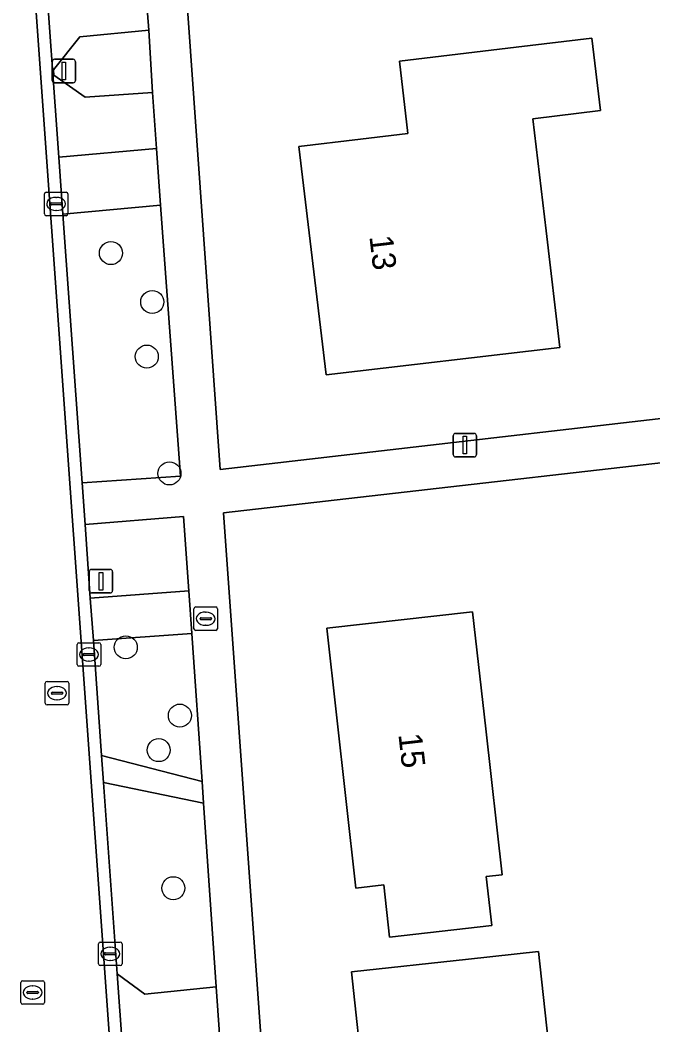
# Model space of a CAD drawing. Extents: x 162661 to 163484, y 380247 to 381230.
# Drawn here: x 163028.8 to 163055.7, y 380630.33 to 380673.06 of the extents above; entities that cross this region are included whole.
import ezdxf

# ---------------------------------------------------------------- set-up
doc = ezdxf.new("R2010")
doc.units = 0
for name, color, linetype in [('IMGEO_Boom', 7, 'Continuous'), ('IMGEO_Brandkraan', 7, 'Continuous'), ('IMGEO_Erf', 7, 'Continuous'), ('IMGEO_Groenvoorziening', 7, 'Continuous'), ('IMGEO_Kolk', 7, 'Continuous'), ('IMGEO_Lichtmast', 7, 'Continuous'), ('IMGEO_Pand', 7, 'Continuous'), ('IMGEO_Pand_nummerreeks', 7, 'Continuous'), ('IMGEO_Rijbaan_lokaal_gesloten', 7, 'Continuous'), ('IMGEO_Rijbaan_lokaal_open', 7, 'Continuous'), ('IMGEO_Rioolput', 7, 'Continuous'), ('IMGEO_Voetpad_halfverhard', 7, 'Continuous'), ('IMGEO_Voetpad_open', 7, 'Continuous')]:
    doc.layers.add(name, color=color, linetype=linetype)

msp = doc.modelspace()

# ---------------------------------------------------------------- linework, layer by layer
at = {"layer": 'IMGEO_Boom'}
for centre in [(163032.664, 380663.15), (163034.421, 380661.073), (163034.19, 380658.75), (163035.153, 380653.782), (163033.297, 380646.386), (163035.594, 380643.483), (163034.695, 380642.014), (163035.315, 380636.144)]:
    msp.add_circle(centre, 0.489, dxfattribs=at)
at = {"layer": 'IMGEO_Brandkraan'}
for p, q in [((163036.194, 380647.178), (163036.194, 380648.03)), ((163036.269, 380648.104), (163037.121, 380648.104)), ((163037.195, 380648.03), (163037.195, 380647.178)), ((163036.453, 380647.598), (163036.453, 380647.61)), ((163036.891, 380647.561), (163036.493, 380647.561)), ((163036.496, 380647.647), (163036.894, 380647.647)), ((163036.682, 380647.884), (163036.707, 380647.884)), ((163036.937, 380647.61), (163036.937, 380647.598)), ((163037.121, 380647.104), (163036.269, 380647.104)), ((163036.705, 380647.324), (163036.68, 380647.324))]:
    msp.add_line(p, q, dxfattribs=at)
for points in [[(163036.194, 380647.178), (163036.194, 380648.03)], [(163036.269, 380648.104), (163037.121, 380648.104)], [(163037.195, 380648.03), (163037.195, 380647.178)], [(163037.121, 380647.104), (163036.269, 380647.104)]]:
    msp.add_lwpolyline(points, dxfattribs=at)
for centre, radius, start, end in [((163036.271, 380648.028), 0.0765, 91.552, 178.448), ((163036.271, 380648.028), 0.0765, 91.552, 178.448), ((163037.119, 380648.028), 0.0765, 1.552, 88.448), ((163037.119, 380648.028), 0.0765, 1.552, 88.448), ((163036.493, 380647.607), 0.0403, 85.8775, 175.7526), ((163036.49, 380647.597), 0.0366, 178.938, 274.7102), ((163036.894, 380647.604), 0.043, 264.8664, 352.4533), ((163036.898, 380647.609), 0.0386, 1.7309, 96.639), ((163036.271, 380647.18), 0.0765, 181.552, 268.448), ((163036.271, 380647.18), 0.0765, 181.552, 268.448), ((163037.119, 380647.18), 0.0765, 271.552, 358.448), ((163037.119, 380647.18), 0.0765, 271.552, 358.448)]:
    msp.add_arc(centre, radius, start, end, dxfattribs=at)
for centre, major_axis, ratio, start_param, end_param in [((163036.681, 380647.604), (-0.387, 0.002), 0.722429, 4.712389, 7.853982), ((163036.706, 380647.604), (-0.39, 0.002), 0.717154, 1.570796, 4.712389)]:
    msp.add_ellipse(centre, major_axis=major_axis, ratio=ratio, start_param=start_param, end_param=end_param, dxfattribs=at)
at = {"layer": 'IMGEO_Erf'}
for points in [[(163099.255, 380695.881), (163097.801, 380713.922), (163097.793, 380714.023), (163096.429, 380713.908), (163093.637, 380713.673), (163059.39, 380710.863), (163058.898, 380719.038), (163058.632, 380719.002), (163032.944, 380715.524), (163037.315, 380653.943), (163063.757, 380657.004), (163064.055, 380657.039), (163063.669, 380662.881), (163100.129, 380668.22), (163101.186, 380668.378), (163101.16, 380668.743)], [(163051.749, 380659.138), (163041.807, 380657.97), (163040.657, 380667.691), (163043.276, 380667.999), (163045.287, 380668.235), (163044.93, 380671.316), (163049.895, 380671.905), (163053.11, 380672.287), (163053.473, 380669.216), (163050.598, 380668.867), (163051.161, 380664.103)], [(163104.464, 380649.238), (163101.514, 380648.96), (163064.825, 380645.41), (163064.179, 380655.165), (163063.957, 380655.14), (163037.446, 380652.111), (163041.973, 380588.769), (163067.753, 380591.633), (163067.425, 380594.839), (163070.153, 380595.118), (163070.481, 380591.912), (163070.696, 380591.934), (163070.695, 380591.946), (163070.09, 380598.191), (163102.911, 380602.998), (163106.144, 380603.482), (163108.863, 380603.734), (163108.827, 380604.097)], [(163048.855, 380634.556), (163044.512, 380634.066), (163044.263, 380636.282), (163043.081, 380636.149), (163041.839, 380647.198), (163048.04, 380647.895), (163048.599, 380642.927), (163049.297, 380636.718), (163048.621, 380636.642)], [(163053.779, 380623.892), (163048.907, 380623.369), (163043.936, 380622.835), (163042.887, 380632.592), (163047.858, 380633.126), (163050.841, 380633.446), (163051.458, 380627.709), (163053.348, 380627.899)]]:
    msp.add_lwpolyline(points, close=True, dxfattribs=at)
at = {"layer": 'IMGEO_Groenvoorziening'}
for points in [[(163034.276, 380672.634), (163031.344, 380672.349), (163030.219, 380670.946), (163030.236, 380670.715), (163031.568, 380669.787), (163034.437, 380669.985)], [(163031.437, 380653.379), (163035.625, 380653.664), (163034.772, 380665.188), (163030.618, 380664.808)], [(163031.788, 380648.483), (163035.979, 380648.782), (163035.754, 380651.951), (163031.564, 380651.615)], [(163036.108, 380646.971), (163031.918, 380646.673), (163032.268, 380641.786), (163036.538, 380640.676)], [(163036.601, 380639.758), (163032.35, 380640.643), (163032.933, 380632.503), (163034.11, 380631.637), (163037.134, 380631.949)]]:
    msp.add_lwpolyline(points, close=True, dxfattribs=at)
at = {"layer": 'IMGEO_Kolk'}
for p, q in [((163029.834, 380664.815), (163029.834, 380665.667)), ((163029.909, 380665.741), (163030.761, 380665.741)), ((163030.322, 380665.521), (163030.347, 380665.521)), ((163030.835, 380665.667), (163030.835, 380664.815)), ((163030.093, 380665.235), (163030.093, 380665.247)), ((163030.531, 380665.198), (163030.133, 380665.198)), ((163030.136, 380665.284), (163030.534, 380665.284)), ((163030.577, 380665.247), (163030.577, 380665.235)), ((163030.761, 380664.741), (163029.909, 380664.741)), ((163030.345, 380664.961), (163030.32, 380664.961)), ((163031.229, 380645.654), (163031.229, 380646.506)), ((163031.304, 380646.58), (163032.156, 380646.58)), ((163031.717, 380646.36), (163031.742, 380646.36)), ((163032.23, 380646.506), (163032.23, 380645.654)), ((163031.488, 380646.074), (163031.488, 380646.086)), ((163031.926, 380646.037), (163031.528, 380646.037)), ((163031.531, 380646.123), (163031.929, 380646.123)), ((163031.74, 380645.8), (163031.715, 380645.8)), ((163031.972, 380646.086), (163031.972, 380646.074)), ((163032.156, 380645.58), (163031.304, 380645.58)), ((163032.211, 380633.854), (163033.063, 380633.854)), ((163032.136, 380632.928), (163032.136, 380633.78)), ((163032.438, 380633.397), (163032.836, 380633.397)), ((163032.624, 380633.634), (163032.649, 380633.634)), ((163033.137, 380633.78), (163033.137, 380632.928)), ((163032.395, 380633.348), (163032.395, 380633.36)), ((163032.833, 380633.311), (163032.435, 380633.311)), ((163032.647, 380633.074), (163032.622, 380633.074)), ((163032.879, 380633.36), (163032.879, 380633.348)), ((163033.063, 380632.854), (163032.211, 380632.854))]:
    msp.add_line(p, q, dxfattribs=at)
for points in [[(163029.834, 380664.815), (163029.834, 380665.667)], [(163029.909, 380665.741), (163030.761, 380665.741)], [(163030.835, 380665.667), (163030.835, 380664.815)], [(163030.761, 380664.741), (163029.909, 380664.741)], [(163031.229, 380645.654), (163031.229, 380646.506)], [(163031.304, 380646.58), (163032.156, 380646.58)], [(163032.23, 380646.506), (163032.23, 380645.654)], [(163032.156, 380645.58), (163031.304, 380645.58)], [(163032.211, 380633.854), (163033.063, 380633.854)], [(163032.136, 380632.928), (163032.136, 380633.78)], [(163033.137, 380633.78), (163033.137, 380632.928)], [(163033.063, 380632.854), (163032.211, 380632.854)]]:
    msp.add_lwpolyline(points, dxfattribs=at)
for centre, radius, start, end in [((163029.911, 380665.665), 0.0765, 91.552, 178.448), ((163029.911, 380665.665), 0.0765, 91.552, 178.448), ((163030.759, 380665.665), 0.0765, 1.552, 88.448), ((163030.759, 380665.665), 0.0765, 1.552, 88.448), ((163030.133, 380665.244), 0.0403, 85.8775, 175.7526), ((163030.13, 380665.234), 0.0366, 178.938, 274.7102), ((163030.534, 380665.241), 0.043, 264.8664, 352.4533), ((163030.538, 380665.246), 0.0386, 1.7309, 96.639), ((163029.911, 380664.817), 0.0765, 181.552, 268.448), ((163029.911, 380664.817), 0.0765, 181.552, 268.448), ((163030.759, 380664.817), 0.0765, 271.552, 358.448), ((163030.759, 380664.817), 0.0765, 271.552, 358.448), ((163031.306, 380646.504), 0.0765, 91.552, 178.448), ((163031.306, 380646.504), 0.0765, 91.552, 178.448), ((163032.154, 380646.504), 0.0765, 1.552, 88.448), ((163032.154, 380646.504), 0.0765, 1.552, 88.448), ((163031.528, 380646.083), 0.0403, 85.8775, 175.7526), ((163031.525, 380646.073), 0.0366, 178.938, 274.7102), ((163031.929, 380646.08), 0.043, 264.8664, 352.4533), ((163031.933, 380646.085), 0.0386, 1.7309, 96.639), ((163031.306, 380645.656), 0.0765, 181.552, 268.448), ((163031.306, 380645.656), 0.0765, 181.552, 268.448), ((163032.154, 380645.656), 0.0765, 271.552, 358.448), ((163032.154, 380645.656), 0.0765, 271.552, 358.448), ((163032.213, 380633.778), 0.0765, 91.552, 178.448), ((163032.213, 380633.778), 0.0765, 91.552, 178.448), ((163033.061, 380633.778), 0.0765, 1.552, 88.448), ((163033.061, 380633.778), 0.0765, 1.552, 88.448), ((163032.435, 380633.357), 0.0403, 85.8775, 175.7526), ((163032.84, 380633.359), 0.0386, 1.7309, 96.639), ((163032.432, 380633.347), 0.0366, 178.938, 274.7102), ((163032.836, 380633.354), 0.043, 264.8664, 352.4533), ((163032.213, 380632.93), 0.0765, 181.552, 268.448), ((163032.213, 380632.93), 0.0765, 181.552, 268.448), ((163033.061, 380632.93), 0.0765, 271.552, 358.448), ((163033.061, 380632.93), 0.0765, 271.552, 358.448)]:
    msp.add_arc(centre, radius, start, end, dxfattribs=at)
for centre, major_axis, ratio, start_param, end_param in [((163030.321, 380665.241), (-0.387, 0.002), 0.722429, 4.712389, 7.853982), ((163030.346, 380665.241), (-0.39, 0.002), 0.717154, 1.570796, 4.712389), ((163031.716, 380646.08), (-0.387, 0.002), 0.722429, 4.712389, 7.853982), ((163031.741, 380646.08), (-0.39, 0.002), 0.717154, 1.570796, 4.712389), ((163032.623, 380633.354), (-0.387, 0.002), 0.722429, 4.712389, 7.853982), ((163032.648, 380633.354), (-0.39, 0.002), 0.717154, 1.570796, 4.712389)]:
    msp.add_ellipse(centre, major_axis=major_axis, ratio=ratio, start_param=start_param, end_param=end_param, dxfattribs=at)
at = {"layer": 'IMGEO_Lichtmast'}
for p, q in [((163030.168, 380670.491), (163030.168, 380671.291)), ((163030.168, 380671.291), (163030.168, 380670.491)), ((163030.268, 380671.391), (163031.058, 380671.391)), ((163031.058, 380671.391), (163030.268, 380671.391)), ((163031.158, 380671.291), (163031.158, 380670.491)), ((163031.158, 380670.491), (163031.158, 380671.291)), ((163031.058, 380670.391), (163030.268, 380670.391)), ((163030.268, 380670.391), (163031.058, 380670.391)), ((163047.214, 380654.586), (163047.214, 380655.386)), ((163047.214, 380655.386), (163047.214, 380654.586)), ((163047.314, 380655.486), (163048.104, 380655.486)), ((163048.104, 380655.486), (163047.314, 380655.486)), ((163048.204, 380655.386), (163048.204, 380654.586)), ((163048.204, 380654.586), (163048.204, 380655.386)), ((163048.104, 380654.486), (163047.314, 380654.486)), ((163047.314, 380654.486), (163048.104, 380654.486)), ((163031.844, 380649.698), (163032.634, 380649.698)), ((163032.634, 380649.698), (163031.844, 380649.698)), ((163031.744, 380648.798), (163031.744, 380649.598)), ((163031.744, 380649.598), (163031.744, 380648.798)), ((163032.734, 380649.598), (163032.734, 380648.798)), ((163032.734, 380648.798), (163032.734, 380649.598)), ((163032.634, 380648.698), (163031.844, 380648.698)), ((163031.844, 380648.698), (163032.634, 380648.698))]:
    msp.add_line(p, q, dxfattribs=at)
for points in [[(163030.588, 380671.266), (163030.738, 380671.266), (163030.738, 380670.516), (163030.588, 380670.516), (163030.588, 380671.266)], [(163047.634, 380655.361), (163047.784, 380655.361), (163047.784, 380654.611), (163047.634, 380654.611), (163047.634, 380655.361)], [(163032.164, 380649.573), (163032.314, 380649.573), (163032.314, 380648.823), (163032.164, 380648.823), (163032.164, 380649.573)]]:
    msp.add_lwpolyline(points, dxfattribs=at)
for centre, start, end in [((163030.268, 380671.291), 90, 180), ((163030.268, 380671.291), 90, 180), ((163031.058, 380671.291), 0, 90), ((163031.058, 380671.291), 360, 90), ((163030.268, 380670.491), 180, 270), ((163030.268, 380670.491), 180, 270), ((163031.058, 380670.491), 270, 0), ((163031.058, 380670.491), 270, 0), ((163047.314, 380655.386), 90, 180), ((163047.314, 380655.386), 90, 180), ((163048.104, 380655.386), 0, 90), ((163048.104, 380655.386), 360, 90), ((163047.314, 380654.586), 180, 270), ((163047.314, 380654.586), 180, 270), ((163048.104, 380654.586), 270, 0), ((163048.104, 380654.586), 270, 0), ((163031.844, 380649.598), 90, 180), ((163031.844, 380649.598), 90, 180), ((163032.634, 380649.598), 0, 90), ((163032.634, 380649.598), 360, 90), ((163031.844, 380648.798), 180, 270), ((163031.844, 380648.798), 180, 270), ((163032.634, 380648.798), 270, 0), ((163032.634, 380648.798), 270, 0)]:
    msp.add_arc(centre, 0.1, start, end, dxfattribs=at)
at = {"layer": 'IMGEO_Pand'}
for points in [[(163043.276, 380667.999), (163040.657, 380667.691), (163041.807, 380657.97), (163051.749, 380659.138), (163051.161, 380664.103), (163050.598, 380668.867), (163053.473, 380669.216), (163053.11, 380672.287), (163049.895, 380671.905), (163044.93, 380671.316), (163045.287, 380668.235)], [(163048.855, 380634.556), (163048.621, 380636.642), (163049.297, 380636.718), (163048.599, 380642.927), (163048.04, 380647.895), (163041.839, 380647.198), (163043.081, 380636.149), (163044.263, 380636.282), (163044.512, 380634.066)], [(163043.936, 380622.835), (163048.907, 380623.369), (163053.779, 380623.892), (163053.348, 380627.899), (163051.458, 380627.709), (163050.841, 380633.446), (163047.858, 380633.126), (163042.887, 380632.592)]]:
    msp.add_lwpolyline(points, close=True, dxfattribs=at)
at = {"layer": 'IMGEO_Rijbaan_lokaal_gesloten'}
msp.add_lwpolyline([(163045.357, 380450.111), (163037.801, 380557.176), (163035.712, 380586.364), (163022.717, 380767.964)], dxfattribs=at)
at = {"layer": 'IMGEO_Rijbaan_lokaal_open'}
msp.add_lwpolyline([(163033.271, 380627.788), (163032.933, 380632.503), (163032.35, 380640.643), (163032.268, 380641.786), (163031.918, 380646.673), (163031.788, 380648.483), (163031.564, 380651.615), (163031.437, 380653.379), (163030.618, 380664.808), (163030.444, 380667.23), (163029.807, 380676.123), (163028.549, 380693.672), (163028.375, 380696.096), (163028.189, 380698.698), (163028.013, 380701.152), (163027.041, 380714.717), (163026.915, 380716.475), (163026.708, 380719.363), (163026.572, 380721.261), (163023.223, 380767.983), (163022.669, 380775.611), (163022.107, 380776.024), (163022.717, 380767.964), (163035.712, 380586.364)], dxfattribs=at)
at = {"layer": 'IMGEO_Rioolput'}
for p, q in [((163029.949, 380644.938), (163030.801, 380644.938)), ((163029.874, 380644.012), (163029.874, 380644.864)), ((163030.176, 380644.481), (163030.574, 380644.481)), ((163030.362, 380644.718), (163030.387, 380644.718)), ((163030.875, 380644.864), (163030.875, 380644.012)), ((163030.133, 380644.432), (163030.133, 380644.444)), ((163030.571, 380644.395), (163030.173, 380644.395)), ((163030.385, 380644.158), (163030.36, 380644.158)), ((163030.617, 380644.444), (163030.617, 380644.432)), ((163030.801, 380643.938), (163029.949, 380643.938)), ((163028.837, 380631.28), (163028.837, 380632.132)), ((163028.912, 380632.206), (163029.764, 380632.206)), ((163029.838, 380632.132), (163029.838, 380631.28)), ((163029.096, 380631.7), (163029.096, 380631.712)), ((163029.534, 380631.663), (163029.136, 380631.663)), ((163029.139, 380631.749), (163029.537, 380631.749)), ((163029.325, 380631.986), (163029.35, 380631.986)), ((163029.58, 380631.712), (163029.58, 380631.7)), ((163029.348, 380631.426), (163029.323, 380631.426)), ((163029.764, 380631.206), (163028.912, 380631.206))]:
    msp.add_line(p, q, dxfattribs=at)
for points in [[(163029.949, 380644.938), (163030.801, 380644.938)], [(163029.874, 380644.012), (163029.874, 380644.864)], [(163030.875, 380644.864), (163030.875, 380644.012)], [(163030.801, 380643.938), (163029.949, 380643.938)], [(163028.837, 380631.28), (163028.837, 380632.132)], [(163028.912, 380632.206), (163029.764, 380632.206)], [(163029.838, 380632.132), (163029.838, 380631.28)], [(163029.764, 380631.206), (163028.912, 380631.206)]]:
    msp.add_lwpolyline(points, dxfattribs=at)
for centre, radius, start, end in [((163029.951, 380644.862), 0.0765, 91.552, 178.448), ((163029.951, 380644.862), 0.0765, 91.552, 178.448), ((163030.799, 380644.862), 0.0765, 1.552, 88.448), ((163030.799, 380644.862), 0.0765, 1.552, 88.448), ((163030.173, 380644.441), 0.0403, 85.8775, 175.7526), ((163030.578, 380644.443), 0.0386, 1.7309, 96.639), ((163030.17, 380644.431), 0.0366, 178.938, 274.7102), ((163030.574, 380644.438), 0.043, 264.8664, 352.4533), ((163029.951, 380644.014), 0.0765, 181.552, 268.448), ((163029.951, 380644.014), 0.0765, 181.552, 268.448), ((163030.799, 380644.014), 0.0765, 271.552, 358.448), ((163030.799, 380644.014), 0.0765, 271.552, 358.448), ((163028.914, 380632.13), 0.0765, 91.552, 178.448), ((163028.914, 380632.13), 0.0765, 91.552, 178.448), ((163029.762, 380632.13), 0.0765, 1.552, 88.448), ((163029.762, 380632.13), 0.0765, 1.552, 88.448), ((163029.136, 380631.709), 0.0403, 85.8775, 175.7526), ((163029.133, 380631.699), 0.0366, 178.938, 274.7102), ((163029.537, 380631.706), 0.043, 264.8664, 352.4533), ((163029.541, 380631.711), 0.0386, 1.7309, 96.639), ((163028.914, 380631.282), 0.0765, 181.552, 268.448), ((163028.914, 380631.282), 0.0765, 181.552, 268.448), ((163029.762, 380631.282), 0.0765, 271.552, 358.448), ((163029.762, 380631.282), 0.0765, 271.552, 358.448)]:
    msp.add_arc(centre, radius, start, end, dxfattribs=at)
for centre, major_axis, ratio, start_param, end_param in [((163030.361, 380644.438), (-0.387, 0.002), 0.722429, 4.712389, 7.853982), ((163030.386, 380644.438), (-0.39, 0.002), 0.717154, 1.570796, 4.712389), ((163029.324, 380631.706), (-0.387, 0.002), 0.722429, 4.712389, 7.853982), ((163029.349, 380631.706), (-0.39, 0.002), 0.717154, 1.570796, 4.712389)]:
    msp.add_ellipse(centre, major_axis=major_axis, ratio=ratio, start_param=start_param, end_param=end_param, dxfattribs=at)
at = {"layer": 'IMGEO_Voetpad_halfverhard'}
msp.add_lwpolyline([(163034.603, 380667.596), (163030.444, 380667.23), (163030.618, 380664.808), (163034.772, 380665.188)], close=True, dxfattribs=at)
at = {"layer": 'IMGEO_Voetpad_open'}
for points in [[(163070.497, 380590.125), (163070.867, 380590.166), (163070.696, 380591.934), (163070.481, 380591.912), (163067.753, 380591.633), (163041.973, 380588.769), (163037.446, 380652.111), (163063.957, 380655.14), (163064.179, 380655.165), (163064.055, 380657.039), (163063.757, 380657.004), (163037.315, 380653.943), (163032.944, 380715.524), (163058.632, 380719.002), (163058.898, 380719.038), (163058.785, 380720.911), (163058.503, 380720.872), (163032.814, 380717.345), (163030.493, 380750), (163029.443, 380764.786), (163028.665, 380775.858), (163028.488, 380778.563), (163028.12, 380778.882)], [(163034.056, 380675.536), (163034.276, 380672.634), (163034.437, 380669.985), (163034.603, 380667.596), (163034.772, 380665.188), (163035.625, 380653.664), (163031.437, 380653.379), (163031.564, 380651.615), (163035.754, 380651.951), (163035.979, 380648.782), (163036.108, 380646.971), (163036.538, 380640.676), (163036.601, 380639.758), (163037.134, 380631.949), (163037.337, 380629.134)]]:
    msp.add_lwpolyline(points, dxfattribs=at)
for points in [[(163030.444, 380667.23), (163034.603, 380667.596), (163034.437, 380669.985), (163031.568, 380669.787), (163030.236, 380670.715), (163030.219, 380670.946), (163031.344, 380672.349), (163034.276, 380672.634), (163034.056, 380675.536), (163031.055, 380675.22), (163029.807, 380676.123)], [(163031.918, 380646.673), (163036.108, 380646.971), (163035.979, 380648.782), (163031.788, 380648.483)], [(163032.268, 380641.786), (163032.35, 380640.643), (163036.601, 380639.758), (163036.538, 380640.676)], [(163033.271, 380627.788), (163034.361, 380628.811), (163037.337, 380629.134), (163037.134, 380631.949), (163034.11, 380631.637), (163032.933, 380632.503)]]:
    msp.add_lwpolyline(points, close=True, dxfattribs=at)

# ---------------------------------------------------------------- texts
at = {"layer": 'IMGEO_Pand_nummerreeks'}
for s, rotation, p in [('13', 276.7468, (163043.648, 380663.857)), ('15', 276.4136, (163044.882, 380642.686))]:
    msp.add_text(s, height=1, rotation=rotation, dxfattribs=at).set_placement(p)

doc.saveas('drawing.dxf')
